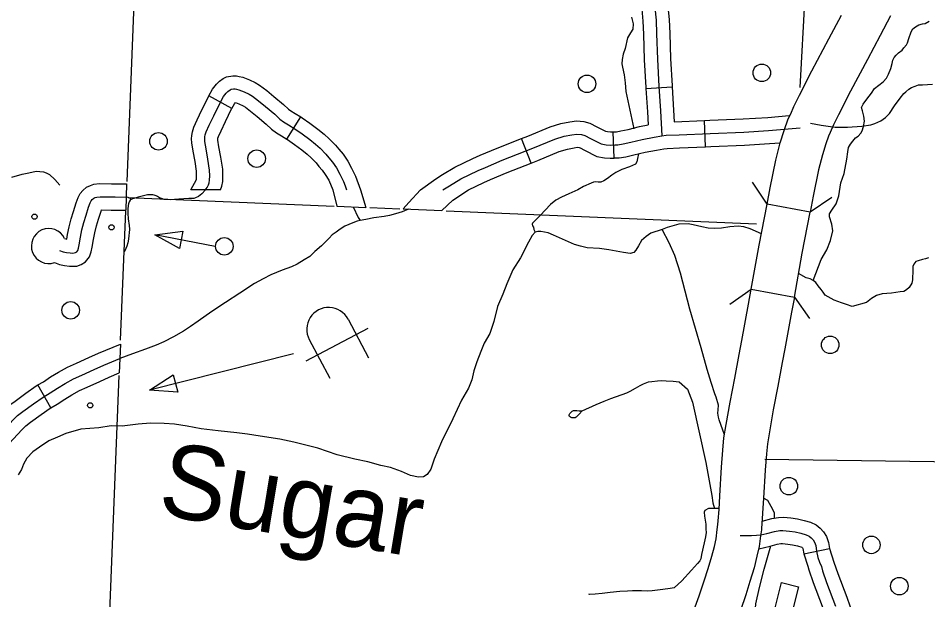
# Model space of a CAD drawing. Extents: x 653372 to 905732, y 627442 to 787275.
# Drawn here: x 684356 to 689553, y 764152 to 767471 of the extents above; entities that cross this region are included whole.
import ezdxf

# ---------------------------------------------------------------- set-up
doc = ezdxf.new("R2010")
doc.units = 0
for name, color, linetype in [('10', 7, 'Continuous'), ('32', 7, 'Continuous'), ('33', 7, 'Continuous'), ('34', 7, 'Continuous'), ('35', 7, 'Continuous'), ('37', 7, 'Continuous'), ('45', 7, 'Continuous'), ('5', 7, 'Continuous'), ('56', 7, 'Continuous'), ('57', 7, 'Continuous'), ('6', 7, 'Continuous')]:
    doc.layers.add(name, color=color, linetype=linetype)

msp = doc.modelspace()

# ---------------------------------------------------------------- linework, layer by layer
at = {"layer": '10'}
for points in [[(688880.1, 766363.9), (688634.5, 766410.9), (688652.2, 766503.2), (688683.9, 766661.9), (688709.8, 766760.4), (688731.5, 766831.3), (688754.3, 766896.8), (688769.2, 766926.3), (688787.7, 766968), (688818.8, 767031.3), (688889.1, 767170.7), (688986.9, 767354.1), (689059.9, 767489.1)], [(689339.3, 767484.6), (689280.8, 767372), (689207.2, 767235.8), (689111, 767055.6), (689042.6, 766919.9), (689014.3, 766862.3), (688995.2, 766819.2), (688984.9, 766798.9), (688969.2, 766753.6), (688950.3, 766692), (688927.6, 766605.6), (688897.6, 766455.2), (688880.1, 766363.9)], [(688544.2, 765924.6), (688589.7, 766176.7), (688634.5, 766410.9)], [(688790.3, 765880.2), (688835.5, 766131), (688880.1, 766363.9)], [(688364.8, 764746.5), (688373.7, 764909.9), (688381.5, 765005.9), (688387.9, 765075.8), (688401.3, 765153.4), (688422.8, 765280.1), (688449.3, 765417.1), (688474.1, 765552.9), (688490.1, 765632.3), (688528.7, 765838.7), (688544.2, 765924.6), (688790.3, 765880.2)], [(688790.3, 765880.2), (688774.6, 765793.5), (688735.5, 765584.7), (688719.7, 765505.8), (688695, 765370.8), (688668.8, 765235.5), (688647.7, 765111.3), (688636, 765043.1), (688630.6, 764984.4), (688623.2, 764893), (688614.4, 764732.9)], [(688207.8, 764071), (688246.1, 764174.1), (688274.9, 764259.8), (688298.1, 764331.7), (688319.6, 764401.2), (688333, 764457.3), (688342.6, 764499.7), (688349.4, 764552.8), (688353.9, 764581.6), (688355.8, 764603.5), (688361, 764668.5), (688364.8, 764746.5)], [(688614.4, 764732.9), (688602.9, 764559.5), (688602.2, 764551.3), (688596.9, 764517.5), (688589.1, 764456.4), (688576.6, 764400.8), (688560.9, 764335.1), (688536.5, 764256.3), (688512.3, 764181.5), (688481.8, 764090.7)]]:
    msp.add_lwpolyline(points, dxfattribs=at)
at = {"layer": '32'}
for p, q in [((687942.3, 767070.7), (688092, 767080.4)), ((685576.4, 766955.4), (685445.2, 767028)), ((685890.5, 766780.9), (685970.6, 766907.7)), ((688283.3, 766737.5), (688276.7, 766887.3)), ((687286.7, 766644.9), (687232, 766784.5)), ((687760.4, 766673.5), (687754.9, 766823.4)), ((685511.9, 766491.2), (685342.7, 766491.1)), ((684541.8, 765247.9), (684468.2, 765378.6)), ((688843.8, 764414.6), (688990.9, 764444.6))]:
    msp.add_line(p, q, dxfattribs=at)
for points in [[(687912.2, 767599.2), (687912.7, 767588.7), (687918.7, 767523.2), (687925.2, 767454.8), (687928.1, 767380), (687932.5, 767234.4), (687941.9, 767076.7), (687942.3, 767070.7)], [(688062.1, 767605.9), (688062.4, 767598.9), (688068.1, 767537.1), (688074.9, 767464.8), (688078, 767385.1), (688082.4, 767241.1), (688091.6, 767086), (688092, 767080.4)], [(687993.4, 767530.2), (688000.1, 767459.8), (688003, 767382.6), (688007.4, 767237.7), (688016.8, 767081.4), (688025.7, 766942.2), (688032.9, 766799.9)], [(685445.2, 767028), (685466.6, 767066.7), (685488.7, 767094.7), (685506.4, 767112.1), (685527.8, 767126.6), (685546.5, 767137.4), (685581.6, 767143.1), (685603.4, 767142.5), (685618.5, 767139.4), (685639, 767135), (685677.2, 767119.7), (685709.5, 767104), (685735.2, 767090.1), (685775.9, 767059.6), (685817.4, 767025.5), (685872.2, 766978.8), (685899.6, 766952.8), (685913.7, 766942.5), (685938.9, 766927.7), (685970.6, 766907.7)], [(685425.7, 766491.1), (685429.7, 766497.1), (685435.1, 766505.8), (685442.6, 766519.9), (685447, 766532), (685449.7, 766547.7), (685450.4, 766571.3), (685449.5, 766604.2), (685440.3, 766666.1), (685429.2, 766725.5), (685422.4, 766768.1), (685421.7, 766782.8), (685422.4, 766794.3), (685424.2, 766804.9), (685429.9, 766822.4), (685446.9, 766861), (685472.9, 766915), (685509, 766988.4), (685529.2, 767025.1), (685544.6, 767044.5), (685554.1, 767053.8), (685567.6, 767063), (685572.1, 767065.6), (685586.6, 767068), (685594.7, 767067.7), (685603.1, 767066), (685617, 767063), (685646.9, 767051), (685675.2, 767037.3), (685694.7, 767026.7), (685729.7, 767000.6), (685769.2, 766968.1), (685822.1, 766922.9), (685851.5, 766895.1), (685872.4, 766879.8), (685899.9, 766863.6), (685936.1, 766840.8), (685978, 766810.8), (686022, 766778.8), (686055.5, 766751.8), (686081, 766728.9), (686112.8, 766696.2), (686131.5, 766674.7), (686152.1, 766650.1), (686174.4, 766616.9), (686192.8, 766581.4), (686214.1, 766539.6), (686223.6, 766514.2), (686232.1, 766491.5)], [(687942.3, 767070.7), (687950.8, 766937.9), (687954.6, 766862.6)], [(688092, 767080.4), (688100.6, 766946.5), (688103.9, 766879.7)], [(685342.7, 766491.1), (685373.8, 766550.4), (685374.2, 766551.3), (685374.8, 766555.2), (685375.3, 766571.5), (685374.7, 766597.7), (685366.3, 766653.7), (685355.3, 766712.6), (685347.6, 766760.4), (685346.6, 766783.5), (685347.8, 766802.8), (685351.2, 766822.8), (685359.7, 766849.2), (685378.8, 766892.4), (685405.4, 766947.8), (685442.5, 767023.1), (685445.2, 767028)], [(685576.4, 766955.4), (685591.9, 766983.4), (685597.2, 766990.1), (685616.5, 766982.4), (685641, 766970.5), (685654.1, 766963.4), (685683.4, 766941.5), (685721.1, 766910.6), (685771.9, 766867.1), (685803.3, 766837.5), (685831.1, 766817), (685860.9, 766799.5), (685890.5, 766780.9)], [(685511.9, 766491.2), (685519.8, 766512.6), (685524.5, 766540.3), (685525.4, 766571.2), (685524.4, 766610.7), (685514.3, 766678.5), (685503.1, 766738.3), (685497.1, 766775.7), (685496.8, 766782.2), (685497, 766785.7), (685497.2, 766787), (685500.1, 766795.7), (685515, 766829.6), (685540.3, 766882.2), (685575.5, 766953.7), (685576.4, 766955.4)], [(685970.6, 766907.7), (685978, 766903), (686021.8, 766871.6), (686067.6, 766838.4), (686104.1, 766808.8), (686132.9, 766783), (686168, 766747), (686188.5, 766723.4), (686212.2, 766695.2), (686239, 766655.2), (686259.5, 766615.6), (686282.8, 766569.9), (686312.3, 766491.5), (686341.6, 766391.8)], [(687232, 766784.5), (687268.1, 766798.7), (687396, 766850.9), (687456.9, 766870.4), (687506.8, 766880.2), (687545.4, 766885.8), (687588.1, 766881.9), (687621.6, 766872.5), (687660.8, 766852.3), (687711, 766826.1), (687723.3, 766824), (687740.7, 766822.9), (687754.9, 766823.4)], [(688103.9, 766879.7), (688276.7, 766887.3)], [(688276.7, 766887.3), (688306.6, 766888.6), (688496.8, 766896.8), (688637.7, 766905.6), (688760.9, 766915.9)], [(686781.9, 766491.7), (686819.6, 766515.3), (686885.7, 766554.4), (686984.6, 766602.1), (687025.4, 766620.2), (687120.6, 766660.4), (687296, 766729.1), (687421.6, 766780.4), (687475.5, 766797.7), (687519.3, 766806.2), (687547.4, 766810.3), (687574.4, 766807.8), (687594, 766802.3), (687626.4, 766785.7), (687686.6, 766754.3), (687714.3, 766749.4), (687739.8, 766747.8), (687764.5, 766748.7), (687781.7, 766749), (687813.1, 766754.6), (687856.9, 766764), (687921.5, 766780.1), (687990.1, 766792.9), (688032.9, 766799.9), (688057, 766803.2), (688131.8, 766805.9), (688309.9, 766813.7), (688500.7, 766821.9), (688643.1, 766830.8), (688823.5, 766845.8)], [(687754.9, 766823.4), (687762.4, 766823.7), (687774.4, 766823.9), (687798.6, 766828.2), (687840, 766837.1), (687905.6, 766853.5), (687954.6, 766862.6)], [(685890.5, 766780.9), (685894.2, 766778.5), (685934.1, 766749.9), (685976.4, 766719.3), (686006.8, 766694.7), (686029, 766674.7), (686057.6, 766645.4), (686074.5, 766625.9), (686092.1, 766604.9), (686109.7, 766578.7), (686130.8, 766546.8), (686154.4, 766491.5), (686175.6, 766398.8), (686341.6, 766391.8)], [(686556, 766382.8), (686588.1, 766419.4), (686653.6, 766491.7), (686742.2, 766555.4), (686780.6, 766579.4), (686850.2, 766620.6), (686953.2, 766670.2), (686995.6, 766689), (687092.3, 766729.8), (687232, 766784.5)], [(687286.7, 766644.9), (687323.9, 766659.4), (687447.3, 766709.8), (687494.2, 766724.9), (687531.9, 766732.2), (687549.5, 766734.8), (687560.8, 766733.8), (687566.4, 766732.2), (687591.9, 766719.1), (687662.1, 766682.5), (687705.4, 766674.8), (687738.8, 766672.7), (687760.4, 766673.5)], [(687760.4, 766673.5), (687766.5, 766673.7), (687789, 766674.1), (687827.6, 766681), (687873.9, 766690.9), (687937.5, 766706.8), (688003, 766719), (688044, 766725.8), (688063.4, 766728.4), (688134.8, 766730.9), (688283.3, 766737.5)], [(688283.3, 766737.5), (688313.1, 766738.8), (688504.7, 766747), (688648.6, 766756), (688710, 766761.1)], [(686556, 766382.8), (686777.2, 766373.5), (686839.5, 766433.7), (686928.6, 766491.8), (687016.1, 766534), (687055.2, 766551.3), (687148.8, 766590.9), (687286.7, 766644.9)], [(684468.2, 765378.6), (684500.1, 765396.6), (684540.9, 765423.8), (684586.7, 765451.9), (684638.6, 765480.8), (684688.9, 765503.1), (684760.1, 765534.7), (684815.3, 765559.9), (684940, 765612), (684933.5, 765446.7)], [(684164.6, 765004), (684223.8, 765066.4), (684324.6, 765177.6), (684351.8, 765203.2), (684382.4, 765226), (684442.9, 765270.1), (684498.4, 765309.5), (684539.4, 765332.7), (684581.3, 765360.6), (684624.6, 765387.2), (684672, 765413.6), (684719.3, 765434.5), (684791, 765466.4), (684845.3, 765491.2), (684936.7, 765529.4)], [(684541.8, 765247.9), (684578.7, 765268.7), (684621.8, 765297.5), (684662.5, 765322.4), (684705.5, 765346.4), (684749.7, 765365.9), (684821.8, 765398), (684875.4, 765422.5), (684933.5, 765446.7)], [(684064.8, 765004.4), (684109.3, 765054.6), (684168.8, 765117.4), (684271, 765230.1), (684303.5, 765260.8), (684337.9, 765286.4), (684399.1, 765331), (684458.1, 765372.9), (684468.2, 765378.6)], [(684177.1, 764905), (684219.9, 764953.3), (684278.8, 765015.4), (684378.1, 765125), (684400, 765145.6), (684426.9, 765165.6), (684486.7, 765209.2), (684538.6, 765246.1), (684541.8, 765247.9)], [(688605.7, 764601.6), (688661.4, 764616.5), (688699.7, 764622.4), (688727.5, 764623.1), (688770.1, 764619.5), (688809, 764614.2), (688846.9, 764604.5), (688883.3, 764594.4), (688914.7, 764580.1), (688938.5, 764561.1), (688956.7, 764540.9), (688974, 764514.3), (688985, 764479.5), (688990.9, 764444.6)], [(688481.5, 764520), (688502.3, 764519.9), (688546, 764519.1), (688574.4, 764520.7), (688599.3, 764523.5), (688633.3, 764531.4), (688676.9, 764543), (688706.3, 764547.6), (688725.2, 764548), (688761.9, 764544.9), (688794.5, 764540.5), (688827.6, 764532), (688857.6, 764523.7), (688875.3, 764515.7), (688886.9, 764506.4), (688897, 764495.1), (688905.5, 764482), (688911.9, 764461.9), (688917.4, 764429.4), (688924.7, 764393.4), (688933.4, 764366.8), (688944.4, 764342.5), (688950.6, 764318.4), (688974.4, 764250.6), (689024.5, 764115.4)], [(688587.5, 764443.7), (688651.5, 764458.6), (688692.4, 764469.5), (688713, 764472.7), (688722.9, 764472.9), (688753.7, 764470.3), (688780.1, 764466.7), (688808.2, 764459.5), (688832, 764452.9), (688835.5, 764451.3), (688837.1, 764449.5), (688838.8, 764444.3), (688843.8, 764414.6)], [(688990.9, 764444.6), (689016.6, 764367), (689039.1, 764302.8), (689089.2, 764167.7), (689106.5, 764118.6), (689143.6, 764028.8), (689150.6, 764001.1), (689155.3, 763958.6)], [(688843.8, 764414.6), (688867.6, 764344.2), (688873, 764323.3), (688898, 764251.9), (688948.1, 764116.6), (688966.4, 764065), (688998, 763988.3)]]:
    msp.add_lwpolyline(points, dxfattribs=at)
at = {"layer": '33'}
for points in [[(688882.2, 766872.7), (688943.6, 766860.3), (689022.7, 766848.9), (689093.2, 766849.8), (689175.9, 766854.8), (689227.2, 766863.8), (689249.8, 766869.8), (689284.1, 766886.1), (689311.6, 766905.5), (689334, 766927.3), (689363.1, 766970.7), (689395.2, 767015.5), (689416.2, 767041.1), (689426.3, 767052.1), (689444, 767066.5), (689460, 767076.6), (689479.7, 767084.2), (689500.2, 767090.4), (689522, 767092), (689579, 767094.7)], [(688361.4, 764672.6), (688300.4, 764672.8), (688279.4, 764662.5), (688275.3, 764652.5), (688276.6, 764629.7), (688283.7, 764584), (688285.2, 764555.6), (688286.5, 764536.1), (688283.4, 764511.2), (688275.3, 764478.3), (688259.6, 764410.6), (688255.5, 764385.9), (688250.4, 764374.2), (688237.7, 764359), (688202.3, 764320.8), (688146.4, 764260.4), (688104.1, 764220.6)], [(688104.1, 764220.6), (688080.4, 764216.5), (688038.6, 764210.2), (687977.4, 764203.5), (687948.9, 764202), (687917.2, 764202.9), (687888.9, 764204.3), (687865.2, 764203.1), (687836.1, 764202.1), (687793.9, 764199.1), (687737.4, 764193.2), (687691.3, 764187.5), (687651.4, 764183.5), (687620.7, 764183), (687616.3, 764183.6)]]:
    msp.add_lwpolyline(points, dxfattribs=at)
at = {"layer": '34'}
for points in [[(685425.7, 766491.1), (685404.5, 766469.2), (685385.5, 766454.4), (685369.9, 766446.6), (685358.6, 766442.9), (685346.3, 766441.6), (685330, 766441.8), (685273.8, 766437.8), (685223.8, 766435.8), (685190.2, 766437.4), (685175.5, 766441.6), (685162.5, 766446.8), (685151.5, 766453.1), (685144, 766457.9), (685132.4, 766462), (685124.7, 766463.9), (685113.9, 766464.3), (685095.6, 766462.5), (685064.5, 766456.3), (685041.4, 766449.9), (685016.6, 766442.6), (685009.2, 766440.6), (685002.2, 766437.1), (684996.6, 766432.1), (684990.9, 766423.4), (684986.5, 766412.8), (684983.9, 766401.7), (684982, 766381.3), (684982.1, 766357.6), (684984.6, 766327.3), (684990.3, 766288), (684991.1, 766267.7), (684990.2, 766245.7), (684988.6, 766230.6), (684986, 766209.5), (684981.9, 766188.7), (684976.2, 766170.1), (684970.7, 766156.8), (684966.7, 766147.8), (684960.9, 766139.1)], [(685002.2, 766437.1), (684993.5, 766444.8), (684983.6, 766449.1), (684972.4, 766450.6)], [(686586.3, 766381.5), (686550.1, 766367), (686511.7, 766355.1), (686477.8, 766345.5), (686446.4, 766339.6), (686387, 766331.4), (686341.8, 766323.4), (686310.5, 766317.5), (686292.3, 766312.4), (686267.1, 766303.2), (686221.3, 766283.7), (686195.9, 766268.2), (686171.7, 766250.9), (686150.6, 766234.7), (686132.6, 766215.3), (686088.3, 766171.7), (686051.2, 766139.1), (686022.3, 766112), (685989.9, 766092.3), (685949.3, 766068), (685918.3, 766053.3), (685864.1, 766033.2), (685799.7, 766006.7), (685756.1, 765984.4), (685706, 765957.2), (685622.7, 765902.9), (685541.3, 765849.9), (685461.9, 765798), (685384.8, 765742.4), (685340.9, 765711.9), (685300.2, 765686.1), (685242.5, 765652.9), (685188.7, 765624.6), (685145.1, 765605.3), (685083.9, 765582.2), (685008.3, 765555.8), (684936.7, 765529.4)], [(686268.9, 766394.9), (686298.2, 766334.2), (686310.5, 766317.5)], [(687578.6, 765229.8), (687658.6, 765266.9), (687702.7, 765286.4), (687742.1, 765300.6), (687769.1, 765310.7), (687805.8, 765324.1), (687833.5, 765333.7), (687851.9, 765342.7), (687882.8, 765359.4), (687909.1, 765375.4), (687928.8, 765384.3), (687956.4, 765396.6), (687976.4, 765398.8), (688008.7, 765401.9), (688033.6, 765403.8), (688058.1, 765402.6), (688098.1, 765400.5), (688131.3, 765396.4), (688179.2, 765354.3), (688208.8, 765280.2)], [(688208.8, 765280.2), (688284.4, 764936.6), (688292.7, 764893.2), (688318.1, 764746.8), (688324.5, 764706.3), (688333.2, 764672.7)], [(687578.6, 765229.8), (687560.6, 765211.3), (687544.3, 765194.5), (687537.8, 765191.1), (687533.3, 765189.9), (687519.7, 765191.6), (687512.1, 765193.7), (687505.9, 765198.4), (687504.2, 765202.5), (687504.4, 765208), (687506.8, 765214.7), (687512.9, 765221.8), (687520.8, 765228.8), (687528.6, 765231.7), (687538.6, 765233.2), (687547.3, 765233.4), (687560.8, 765231.2), (687568.5, 765230.1), (687578.6, 765229.8)]]:
    msp.add_lwpolyline(points, dxfattribs=at)
at = {"layer": '35'}
for points in [[(687859, 767477.7), (687870.1, 767439.3), (687866.7, 767408.2), (687853.7, 767387.2), (687837.2, 767358.7), (687823.9, 767298.5), (687813.1, 767266.5), (687805.6, 767235.5), (687804.3, 767210.8), (687808.4, 767191.8), (687818.6, 767148.8), (687822.9, 767101.8), (687827.2, 767053.2), (687873.6, 766840.3)], [(688896.8, 765975.1), (688944, 766094.1), (688975.7, 766148.6), (688997.5, 766202.6), (689010.3, 766257.9), (689004.4, 766296.5), (688990.5, 766337.4), (688990, 766355.6), (689003.7, 766375.5), (689028.1, 766411.2), (689043.6, 766457.2), (689056, 766531.8), (689073.8, 766584.9), (689090.4, 766666.3), (689095.7, 766709.7), (689099.5, 766733.8), (689111.2, 766752.7), (689123.8, 766770.6), (689138.6, 766789.3), (689155, 766799), (689170.7, 766815.7), (689178.2, 766829.6), (689185, 766852.7), (689190, 766884.6), (689186.8, 766912.1), (689178.6, 766942.7), (689173.1, 766962), (689182.8, 766981), (689204.8, 767008.7), (689230.2, 767044.3), (689248.2, 767070.1), (689273, 767088.6), (689296.8, 767107.6), (689316.7, 767129.3), (689328.5, 767152.2), (689341.7, 767185.2), (689349.6, 767213.3), (689352.2, 767232.5), (689359.7, 767247.4), (689371.2, 767261.2), (689384.8, 767274), (689405.5, 767288.5), (689416, 767302.4), (689430.7, 767319.2), (689436.1, 767331.1), (689443.9, 767356.2), (689458.2, 767394.2), (689466.8, 767411.2), (689482.3, 767421.8), (689501.9, 767434.4), (689521.3, 767439.9), (689537.5, 767441.4), (689561.1, 767453.9)], [(687899, 766697.2), (687894.8, 766670.9), (687889.7, 766651.9), (687881.7, 766638.7), (687848, 766623.7), (687804.1, 766608.4), (687770.3, 766590.9), (687746.9, 766575.6), (687723.3, 766557.2), (687701.8, 766542.5), (687684.3, 766536.6), (687670.2, 766535.7), (687653.7, 766537.5), (687642.8, 766535.3), (687628.5, 766530), (687585.8, 766511.4), (687552.6, 766492.6), (687501.5, 766469.8), (687460.6, 766450.6), (687427.1, 766432.5), (687397.5, 766408.1)], [(684318.9, 766564.1), (684378.8, 766582.1), (684416, 766588.9), (684458.2, 766598.2), (684500.3, 766594.3), (684516, 766589.9), (684534.2, 766580.1), (684566.3, 766550.1), (684593.9, 766517.7)], [(687397.5, 766408.1), (687337.8, 766346), (687303.9, 766310.7), (687293.9, 766301.3), (687293.1, 766295.1), (687294.1, 766287.4), (687299.2, 766278), (687302.7, 766266.3), (687309.5, 766250.3)], [(688602.1, 766241.5), (688538.6, 766268.8), (688501.6, 766281.4), (688468.6, 766285.3), (688422.4, 766280.9), (688373.3, 766273.8), (688332.9, 766270.6), (688297, 766273.2), (688261.2, 766280), (688212.7, 766293), (688183.8, 766298.5), (688130.7, 766295.4), (688064, 766277.3), (688034.8, 766265.2), (687970.9, 766245.5), (687942.7, 766225.2), (687917.8, 766202.5), (687899.7, 766172.8), (687884.2, 766147), (687872.3, 766134.4), (687851.3, 766128.6), (687815, 766133.6), (687730.3, 766150.2), (687676.1, 766156.5), (687607.2, 766161.4), (687568.9, 766169.6), (687534.7, 766180.9), (687413.7, 766234.1), (687383.4, 766245.9), (687342.1, 766253.5), (687325.2, 766254.2), (687309.5, 766250.3), (687291.5, 766232.2), (687271.6, 766193.5), (687225.8, 766103.8), (687181.3, 766036), (687148.3, 765956.4), (687124.9, 765896.6), (687094, 765827), (687072.7, 765739.9), (687050.5, 765672.9), (687018.6, 765616.2), (686999.9, 765568.9), (686975.6, 765510.7), (686959.2, 765459.2), (686947.6, 765407.7), (686928.9, 765360.8), (686889.4, 765291.4), (686838.7, 765185), (686774.3, 765053), (686732.5, 764955), (686714.3, 764898), (686691.8, 764867), (686672.4, 764854.7), (686643.8, 764851.2), (686598, 764861.2), (686546.6, 764884.4), (686482.9, 764907.8), (686427.1, 764919.6), (686354.3, 764940.5), (686278.5, 764955.7), (686178.5, 764980.3), (686067.4, 765018.2), (685931.7, 765051.1), (685850.2, 765069.3), (685737.9, 765085.7), (685666.3, 765097.9), (685606.1, 765105.5), (685498.5, 765117.3), (685401, 765128.9), (685322.2, 765142.8), (685249.2, 765155.1), (685190.3, 765158.3), (685111.2, 765160.6), (685042, 765154.1), (684951, 765143.9), (684887.7, 765144.3), (684817.3, 765133.5), (684714.9, 765126.5), (684627.8, 765101.7), (684581.1, 765080.1), (684531.6, 765060), (684477.2, 765024.2), (684440.4, 764996.5), (684406.2, 764960.1), (684386.5, 764926.2), (684374.1, 764896.3), (684355.9, 764865.2)], [(688391.1, 765093.2), (688360.4, 765179.1), (688356.4, 765195.1), (688352.5, 765216.6), (688355.4, 765237.3), (688357, 765262.2), (688343.9, 765308.8), (688335.4, 765327.2), (688315.2, 765392.8), (688291.1, 765467.4), (688257, 765590.9), (688192.3, 765810.2), (688138.9, 766017), (688106.4, 766116.6), (688075.3, 766189.8), (688034.8, 766265.2)], [(689556.9, 766103.1), (689539, 766098.1), (689521.3, 766094.2), (689497.8, 766086.1), (689483.3, 766082.1), (689471.9, 766068.1), (689467, 766053.9), (689466.5, 766035.1), (689465.9, 765978.9), (689460.9, 765959.2), (689446.9, 765935.3), (689429.9, 765921.4), (689416.4, 765911.9), (689395.4, 765910.3), (689344.6, 765903.1), (689292.5, 765898.1), (689260.2, 765889.1), (689229.9, 765871.2), (689201.6, 765848.9), (689120.9, 765825.9), (689087.1, 765837.9), (689058.6, 765847.6), (689018.2, 765862.1), (688966.1, 765890.2), (688954.4, 765908.2), (688943.9, 765924), (688926.8, 765944.4), (688911.9, 765962.5), (688896.8, 765975.1), (688880.5, 765984.4), (688857.5, 765989.5), (688814.4, 766014.2)], [(688676.8, 764618.9), (688676.1, 764649), (688657.2, 764684.4), (688638.4, 764718.2), (688614.4, 764732.5)], [(688486.8, 763758.7), (688519.2, 763887.7), (688562.4, 764024.8), (688571, 764129.3), (688590.3, 764222.2), (688617.4, 764327.1), (688656.3, 764459.9)]]:
    msp.add_lwpolyline(points, dxfattribs=at)
at = {"layer": '37'}
for points in [[(688634.5, 766410.9), (688550.3, 766535.1)], [(689004.2, 766448.1), (688880.1, 766363.9)], [(688421, 765839.1), (688544.2, 765924.6)], [(688790.3, 765880.2), (688875.8, 765757)]]:
    msp.add_lwpolyline(points, dxfattribs=at)
at = {"layer": '45'}
for points in [[(684621.5, 766214.9), (684633.9, 766210.3), (684634, 766210.3), (684637.9, 766236.2), (684647.6, 766280.3), (684659, 766325.8), (684672.2, 766368.9), (684686.9, 766417.2), (684698.2, 766448.4), (684710.2, 766470.8), (684725.6, 766488.8), (684746.5, 766507.7), (684769.8, 766517.6), (684788.8, 766523.8), (684820, 766527.2), (684888.6, 766526.8)], [(684888.6, 766526.8), (684910.2, 766526.7), (684974.6, 766525.4), (684970.2, 766375.5)], [(684592.1, 766145.8), (684613, 766138.1), (684633, 766133.8), (684653.7, 766131.5), (684666.4, 766131.2), (684676.1, 766131.5), (684682.6, 766134), (684690.4, 766138.8), (684696.4, 766146.3), (684700.7, 766158.3), (684705, 766178.4), (684711.7, 766222.5), (684720.6, 766263.1), (684731.3, 766305.7), (684743.9, 766347), (684758.1, 766393.5), (684766.8, 766417.7), (684772.5, 766428.3), (684779.5, 766436.5), (684787.4, 766443.6), (684796.2, 766447.3), (684804.7, 766450.1), (684823.8, 766452.2), (684909.3, 766451.7), (684973.2, 766450.5)], [(684563.6, 766076.4), (684592.1, 766065.9), (684621, 766059.7), (684648.4, 766056.7), (684666.7, 766056.1), (684691.5, 766057.1), (684715.9, 766066.5), (684741, 766081.8), (684762.7, 766109.3), (684773, 766137.4), (684778.8, 766165), (684785.5, 766208.8), (684793.7, 766245.9), (684803.6, 766285.6), (684815.7, 766325.1), (684829.3, 766369.8), (684831.9, 766377.2), (684887.6, 766376.8)], [(684887.6, 766376.8), (684908.3, 766376.7), (684970.2, 766375.5)]]:
    msp.add_lwpolyline(points, dxfattribs=at)
msp.add_arc((684531.6, 766171.1), 100, 25.9525, 288.6441, dxfattribs=at)
at = {"layer": '5'}
msp.add_lwpolyline([(685076.3, 769056.8), (684976.7, 766539.9)], dxfattribs=at)
at = {"layer": '56'}
for p, q in [((685136.2, 766235), (685296, 766256.5)), ((685277, 766156.3), (685136.2, 766235)), ((685296, 766256.5), (685277, 766156.3))]:
    msp.add_line(p, q, dxfattribs=at)
msp.add_lwpolyline([(685480.8, 766169.5), (685136.2, 766235)], dxfattribs=at)
msp.add_lwpolyline([(688716, 764250.3), (688813.1, 764226), (688707, 763801.6), (688610, 763825.8)], close=True, dxfattribs=at)
for centre, radius in [((688604.2, 767159.7), 50), ((687605.5, 767096.8), 50), ((685157.6, 766769), 50), ((685718.7, 766670.1), 50), ((684449.5, 766338.9), 15), ((684889.2, 766278), 15), ((685534.1, 766169.4), 50), ((684656.1, 765804.5), 50), ((688994.9, 765607.1), 50), ((688758.9, 764800.9), 50), ((689230.4, 764465.5), 50), ((689389.5, 764230.3), 50)]:
    msp.add_circle(centre, radius, dxfattribs=at)
at = {"layer": '57'}
for p, q in [((686240.3, 765754.4), (686357.1, 765533.4)), ((686353.3, 765701), (685999.7, 765514.1)), ((686019.3, 765637.6), (686136.1, 765416.6)), ((685106.5, 765349), (685242.3, 765435.9)), ((685242.3, 765435.9), (685267.3, 765337)), ((685267.3, 765337), (685106.5, 765349))]:
    msp.add_line(p, q, dxfattribs=at)
msp.add_lwpolyline([(685929.8, 765556.8), (685106.5, 765349)], dxfattribs=at)
msp.add_circle((684767.7, 765262), 15, dxfattribs=at)
msp.add_arc((686129.8, 765696), 125, 27.8546, 207.8546, dxfattribs=at)
at = {"layer": '6'}
for points in [[(688822.7, 767075.4), (688852.2, 767598.4), (688292.3, 767622.6), (688306.9, 767973.1), (688246.1, 767987.2), (688268.4, 768538), (688329.8, 768535.6), (688406.1, 770275.7), (688214.8, 770270.8), (688193.5, 769796.2), (687727.5, 769816.2), (687733.2, 769937.5)], [(684983.6, 766449.1), (686161.7, 766399.4)], [(684940.8, 765633.6), (684970.1, 766372.1)], [(686365, 766390.8), (686536.6, 766383.6)], [(686801, 766372.5), (688573.2, 766297.7)], [(682934.8, 763901.9), (684855.3, 763817.7), (684868, 763791.8), (684932.9, 765432.1)], [(692625.6, 764780.2), (691426.8, 764857.3), (691386.4, 763499.9), (690104.8, 763569.7), (690138.8, 764932), (688620.9, 764953.1)]]:
    msp.add_lwpolyline(points, dxfattribs=at)

# ---------------------------------------------------------------- texts
at = {"layer": '35'}
msp.add_text('Sugar', height=422.4, rotation=350.5459, dxfattribs=at).set_placement((685144.4, 764641.5))

doc.saveas('drawing.dxf')
